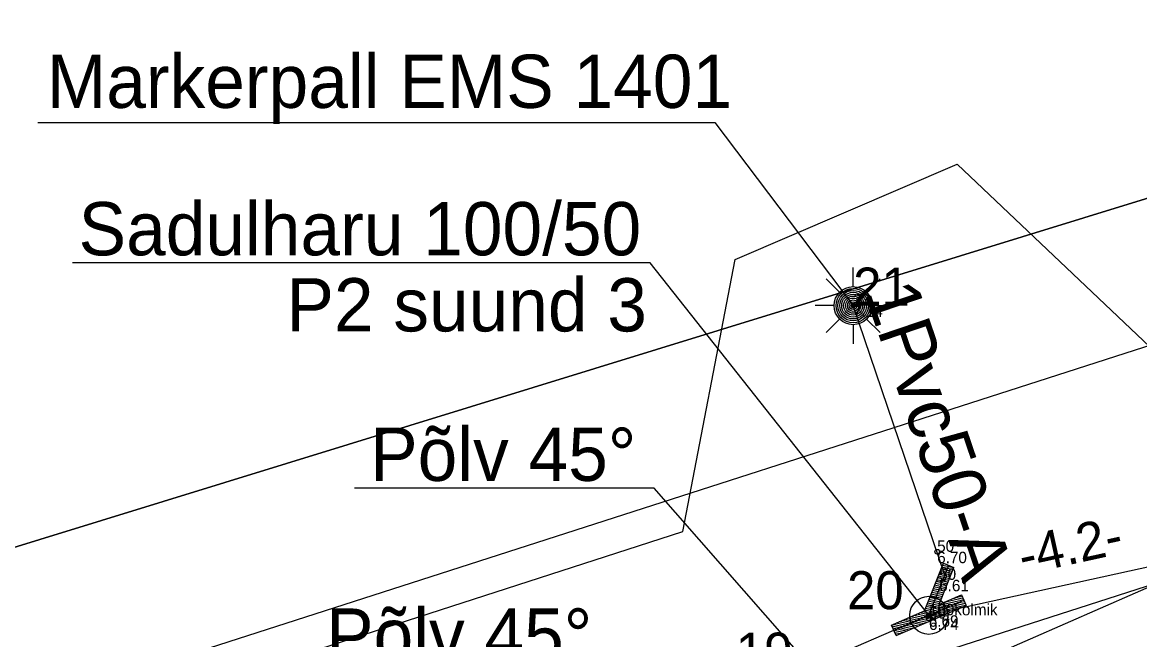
# Model space of a CAD drawing. Extents: x 546339 to 546593, y 6597108 to 6597251.
# Drawn here: x 546468.19 to 546482.86, y 6597191.16 to 6597199.27 of the extents above; entities that cross this region are included whole.
import ezdxf

# ---------------------------------------------------------------- set-up
doc = ezdxf.new("R2010")
doc.units = 0
for name, color, linetype in [('JOONSIDE', 7, 'Continuous'), ('KOORDPUNKT', 7, 'Continuous'), ('MOOTKORG-EH2000', 7, 'Continuous'), ('MOOTMPUNKT', 7, 'Continuous'), ('MOOTNR', 7, 'Continuous'), ('MOOTPIIR', 7, 'Continuous'), ('PIIR', 7, 'Continuous'), ('SITRASS', 7, 'Continuous'), ('TEE', 7, 'Continuous')]:
    doc.layers.add(name, color=color, linetype=linetype)

msp = doc.modelspace()

# ---------------------------------------------------------------- linework, layer by layer
at = {"layer": 'KOORDPUNKT'}
for centre, radius in [((546479.1, 6597195.55), 0.25), ((546479.1, 6597195.55), 0.025), ((546479.1, 6597195.55), 0.0221), ((546479.1, 6597195.55), 0.0191), ((546479.1, 6597195.55), 0.0161), ((546479.1, 6597195.55), 0.0132), ((546479.1, 6597195.55), 0.0102), ((546479.1, 6597195.55), 0.00726), ((546479.1, 6597195.55), 0.0043), ((546480.094, 6597191.481), 0.25), ((546480.094, 6597191.481), 0.025), ((546480.094, 6597191.481), 0.0221), ((546480.094, 6597191.481), 0.0191), ((546480.094, 6597191.481), 0.0161), ((546480.094, 6597191.481), 0.0132), ((546480.094, 6597191.481), 0.0102), ((546480.094, 6597191.481), 0.00726), ((546480.094, 6597191.481), 0.0043)]:
    msp.add_circle(centre, radius, dxfattribs=at)
at = {"layer": 'MOOTMPUNKT'}
for centre in [(546479.1, 6597195.55), (546480.204, 6597192.316), (546480.23, 6597191.947), (546480.094, 6597191.481), (546480.097, 6597191.439)]:
    msp.add_circle(centre, 0.03, dxfattribs=at)
at = {"layer": 'MOOTPIIR'}
msp.add_lwpolyline([(546431.038, 6597182.742), (546435.363, 6597179.169), (546476.861, 6597192.584), (546477.551, 6597196.157), (546480.466, 6597197.411), (546483.506, 6597194.527), (546510.21, 6597203.146)], dxfattribs=at)
at = {"layer": 'PIIR'}
for points in [[(546459.55, 6597209.598), (546466.79, 6597191.98), (546491.04, 6597199.45), (546483.698, 6597217.73)], [(546510.07, 6597205.36), (546491.04, 6597199.45), (546466.79, 6597191.98), (546431.99, 6597181.07), (546399.93, 6597171.7), (546399.49, 6597172.55), (546362.07, 6597160.42), (546350.54, 6597167.22), (546341.457, 6597167.537)]]:
    msp.add_lwpolyline(points, dxfattribs=at)
at = {"layer": 'SITRASS'}
for p, q in [((546479.1, 6597195.8), (546479.1, 6597196.05)), ((546478.923, 6597195.727), (546478.746, 6597195.904)), ((546479.277, 6597195.727), (546479.454, 6597195.904)), ((546478.85, 6597195.55), (546478.6, 6597195.55)), ((546479.35, 6597195.55), (546479.6, 6597195.55)), ((546478.923, 6597195.373), (546478.746, 6597195.196)), ((546479.1, 6597195.3), (546479.1, 6597195.05)), ((546479.277, 6597195.373), (546479.454, 6597195.196)), ((546480.036, 6597191.538), (546480.285, 6597192.166)), ((546480.094, 6597191.481), (546480.355, 6597192.138)), ((546480.231, 6597191.622), (546480.425, 6597192.11)), ((546480.394, 6597192.032), (546480.246, 6597192.066)), ((546480.403, 6597192.056), (546480.255, 6597192.089)), ((546480.412, 6597192.079), (546480.264, 6597192.113)), ((546480.422, 6597192.103), (546480.274, 6597192.136)), ((546480.325, 6597192.15), (546480.283, 6597192.16)), ((546480.285, 6597192.166), (546480.425, 6597192.11)), ((546480.338, 6597191.891), (546480.19, 6597191.925)), ((546480.347, 6597191.914), (546480.199, 6597191.948)), ((546480.356, 6597191.938), (546480.208, 6597191.972)), ((546480.366, 6597191.961), (546480.218, 6597191.995)), ((546480.375, 6597191.985), (546480.227, 6597192.019)), ((546480.384, 6597192.008), (546480.236, 6597192.042)), ((546480.282, 6597191.75), (546480.133, 6597191.783)), ((546480.291, 6597191.773), (546480.143, 6597191.807)), ((546480.3, 6597191.797), (546480.152, 6597191.83)), ((546480.31, 6597191.82), (546480.162, 6597191.854)), ((546480.319, 6597191.844), (546480.171, 6597191.878)), ((546480.328, 6597191.867), (546480.18, 6597191.901)), ((546479.635, 6597191.283), (546480.553, 6597191.679)), ((546480.457, 6597191.556), (546480.077, 6597191.642)), ((546480.235, 6597191.632), (546480.087, 6597191.666)), ((546480.244, 6597191.656), (546480.096, 6597191.689)), ((546480.253, 6597191.679), (546480.105, 6597191.713)), ((546480.263, 6597191.703), (546480.115, 6597191.736)), ((546480.272, 6597191.726), (546480.124, 6597191.76)), ((546480.231, 6597191.622), (546480.523, 6597191.748)), ((546480.496, 6597191.573), (546480.248, 6597191.629)), ((546480.535, 6597191.59), (546480.287, 6597191.646)), ((546480.574, 6597191.606), (546480.326, 6597191.663)), ((546480.573, 6597191.632), (546480.365, 6597191.68)), ((546480.561, 6597191.661), (546480.404, 6597191.696)), ((546480.549, 6597191.689), (546480.443, 6597191.713)), ((546480.537, 6597191.718), (546480.482, 6597191.73)), ((546480.524, 6597191.746), (546480.521, 6597191.747)), ((546480.523, 6597191.748), (546480.583, 6597191.61)), ((546479.605, 6597191.352), (546480.036, 6597191.538)), ((546479.665, 6597191.214), (546480.583, 6597191.61)), ((546480.185, 6597191.439), (546479.937, 6597191.495)), ((546480.224, 6597191.455), (546479.976, 6597191.512)), ((546480.263, 6597191.472), (546480.015, 6597191.528)), ((546480.302, 6597191.489), (546480.04, 6597191.548)), ((546480.341, 6597191.506), (546480.049, 6597191.572)), ((546480.38, 6597191.522), (546480.059, 6597191.595)), ((546480.418, 6597191.539), (546480.068, 6597191.619)), ((546479.665, 6597191.214), (546479.605, 6597191.352)), ((546479.834, 6597191.287), (546479.611, 6597191.338)), ((546479.873, 6597191.304), (546479.625, 6597191.361)), ((546479.912, 6597191.321), (546479.664, 6597191.377)), ((546479.951, 6597191.338), (546479.703, 6597191.394)), ((546479.99, 6597191.355), (546479.742, 6597191.411)), ((546480.029, 6597191.371), (546479.781, 6597191.428)), ((546480.068, 6597191.388), (546479.82, 6597191.444)), ((546480.107, 6597191.405), (546479.859, 6597191.461)), ((546480.146, 6597191.422), (546479.898, 6597191.478)), ((546479.795, 6597191.271), (546479.623, 6597191.31)), ((546479.757, 6597191.254), (546479.636, 6597191.281)), ((546479.718, 6597191.237), (546479.648, 6597191.253)), ((546479.679, 6597191.22), (546479.66, 6597191.224))]:
    msp.add_line(p, q, dxfattribs=at)
for points in [[(546468.388, 6597197.955), (546477.285, 6597197.955), (546479.1, 6597195.55)], [(546480.094, 6597191.481), (546476.434, 6597196.113), (546468.844, 6597196.113)], [(546480.094, 6597191.481), (546480.303, 6597192.007), (546479.1, 6597195.55)], [(546478.539, 6597190.81), (546476.485, 6597193.15), (546472.55, 6597193.15)], [(546478.142, 6597189.676), (546478.67, 6597189.965), (546484.189, 6597192.382)], [(546484.189, 6597192.382), (546480.094, 6597191.481)], [(546480.094, 6597191.481), (546478.539, 6597190.81), (546478.346, 6597190.26), (546478.142, 6597189.676)]]:
    msp.add_lwpolyline(points, dxfattribs=at)
for radius in [0.25, 0.225, 0.2, 0.175, 0.15, 0.125, 0.1, 0.075, 0.05, 0.025]:
    msp.add_circle((546479.1, 6597195.55), radius, dxfattribs=at)
at = {"layer": 'TEE'}
for points in [[(546514.456, 6597205.157), (546396.804, 6597167.285), (546396.804, 6597167.285)], [(546515.375, 6597202.301), (546397.724, 6597164.429), (546397.724, 6597164.429)]]:
    msp.add_lwpolyline(points, dxfattribs=at)

# ---------------------------------------------------------------- texts
at = {"layer": 'JOONSIDE'}
msp.add_text('-4.2-', height=0.5, rotation=12.4088, dxfattribs=at).set_placement((546481.331, 6597192.009))
at = {"layer": 'KOORDPUNKT'}
for s, p in [('21', (546479.1, 6597195.55)), ('20', (546479.02, 6597191.561)), ('19', (546477.56, 6597190.754))]:
    msp.add_text(s, height=0.5, dxfattribs=at).set_placement(p)
at = {"layer": 'MOOTKORG-EH2000'}
for s, p in [('7.14', (546479.1, 6597195.4)), ('6.70', (546480.204, 6597192.166)), ('6.61', (546480.23, 6597191.797)), ('6.69', (546480.094, 6597191.331)), ('6.74', (546480.097, 6597191.289))]:
    msp.add_text(s, height=0.15, dxfattribs=at).set_placement(p)
at = {"layer": 'MOOTNR'}
for s, p in [('33', (546479.1, 6597195.55)), ('50', (546480.204, 6597192.316)), ('50', (546480.23, 6597191.947)), ('100kolmik', (546480.094, 6597191.481)), ('50', (546480.097, 6597191.439))]:
    msp.add_text(s, height=0.15, dxfattribs=at).set_placement(p)
at = {"layer": 'SITRASS'}
for s, p in [('Markerpall EMS 1401', (546468.509, 6597198.148)), ('Sadulharu 100/50', (546468.925, 6597196.211)), ('P2 suund 3', (546471.655, 6597195.211)), ('Põlv 45°', (546472.755, 6597193.247)), ('Põlv 45°', (546472.176, 6597190.871))]:
    msp.add_text(s, height=0.7, dxfattribs=at).set_placement(p)
msp.add_text('1Pvc50-A', height=0.7, rotation=288.7547, dxfattribs=at).set_placement((546479.243, 6597195.726))

doc.saveas('drawing.dxf')
